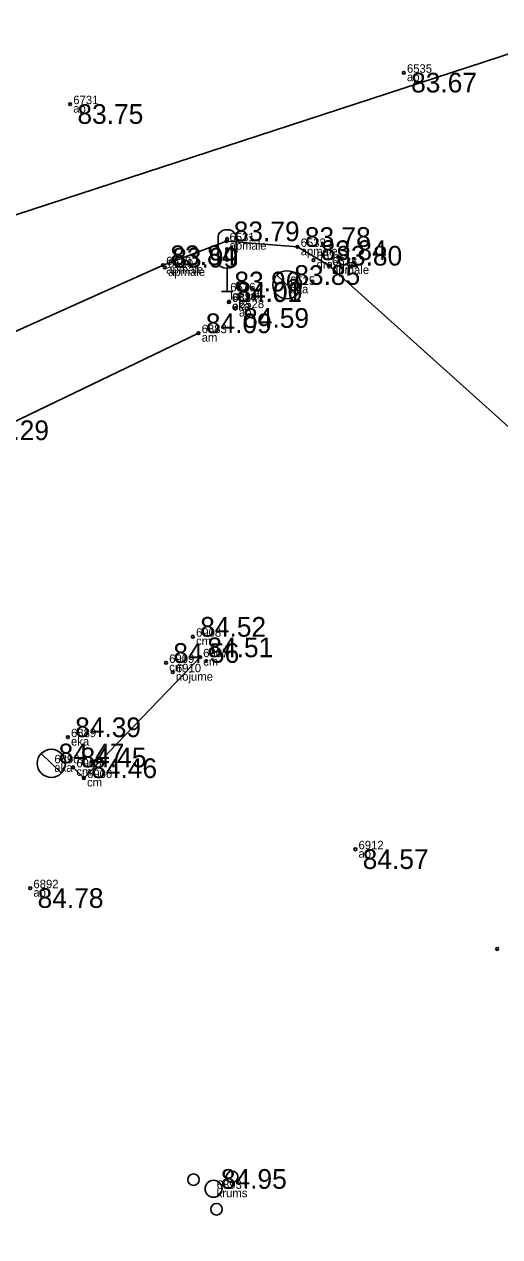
# Model space of a CAD drawing. Extents: x 614911 to 615803, y 262110 to 264311.
# Drawn here: x 615249.41 to 615266.31, y 262526.26 to 262569.35 of the extents above; entities that cross this region are included whole.
import ezdxf

# ---------------------------------------------------------------- set-up
doc = ezdxf.new("R2010")
doc.units = 0
for name, color, linetype in [('Level 1', 7, 'Continuous'), ('Level 12', 7, 'Continuous'), ('Level 16', 7, 'Continuous'), ('Level 37', 7, 'Continuous'), ('Level 53', 7, 'Continuous'), ('Level 54', 7, 'Continuous'), ('Level 57', 7, 'Continuous'), ('Level 58', 7, 'Continuous')]:
    doc.layers.add(name, color=color, linetype=linetype)

msp = doc.modelspace()

# ---------------------------------------------------------------- linework, layer by layer
at = {"layer": 'Level 1'}
for centre, radius in [((615256.802, 262528.386), 0.207), ((615255.427, 262528.285), 0.204), ((615256.141, 262527.961), 0.301), ((615256.244, 262527.233), 0.205)]:
    msp.add_circle(centre, radius, dxfattribs=at)
at = {"layer": 'Level 12'}
for p, q in [((615258.392, 262560.439), (615259.11, 262559.743)), ((615258.751, 262560.091), (615258.75, 262560.09)), ((615250.013, 262543.431), (615250.731, 262542.735)), ((615250.372, 262543.083), (615250.371, 262543.082))]:
    msp.add_line(p, q, dxfattribs=at)
for centre in [(615258.751, 262560.091), (615250.372, 262543.083)]:
    msp.add_circle(centre, 0.5, dxfattribs=at)
at = {"layer": 'Level 16'}
for p, q in [((615256.302, 262561.808), (615256.302, 262560.862)), ((615256.944, 262561.808), (615256.944, 262560.862)), ((615256.623, 262560.688), (615256.623, 262559.859)), ((615256.423, 262559.859), (615256.623, 262559.859)), ((615256.623, 262559.859), (615256.823, 262559.859))]:
    msp.add_line(p, q, dxfattribs=at)
for centre in [(615256.623, 262561.719), (615256.623, 262561.359), (615256.623, 262560.979)]:
    msp.add_circle(centre, 0.05, dxfattribs=at)
for centre, ratio, start_param, end_param in [((615256.623, 262561.808), 0.760342, 0, 3.141593), ((615256.623, 262560.862), 0.542056, 3.141593, 6.283185)]:
    msp.add_ellipse(centre, major_axis=(0.321, 0), ratio=ratio, start_param=start_param, end_param=end_param, dxfattribs=at)
at = {"layer": 'Level 37'}
for points in [[(615457.356, 262631.081), (615418.128, 262618.058), (615393.754, 262609.896), (615371.98, 262602.687), (615338.025, 262591.236), (615307.145, 262581.538), (615241.041, 262559.945), (615223.546, 262552.282)], [(615305.711, 262520.305), (615305.035, 262521.061), (615300.079, 262524.986), (615283.388, 262539.926), (615275.352, 262547.197), (615260.244, 262560.777), (615259.126, 262561.441), (615256.598, 262561.642), (615254.346, 262560.792)], [(615254.346, 262560.792), (615243.383, 262555.871), (615236.021, 262552.487), (615232.793, 262549.846), (615230.539, 262546.557), (615229.608, 262539.718), (615229.798, 262537.742), (615236, 262503.867)], [(615239.65, 262486.346), (615242.619, 262487.458), (615239.15, 262503.973), (615232.793, 262537.845), (615232.824, 262539.909), (615233.444, 262544.601), (615235.556, 262547.934), (615237.603, 262549.605), (615247.69, 262554.573), (615255.607, 262558.375)], [(615255.66, 262546.855), (615251.532, 262542.561), (615251.154, 262542.941)]]:
    msp.add_lwpolyline(points, dxfattribs=at)
at = {"layer": 'Level 57'}
for centre in [(615262.903, 262567.63), (615251.043, 262566.514), (615256.598, 262561.642), (615259.126, 262561.441), (615259.692, 262560.972), (615254.346, 262560.792), (615254.411, 262560.707), (615260.244, 262560.777), (615256.681, 262559.48), (615256.695, 262559.493), (615256.933, 262559.264), (615255.607, 262558.375), (615255.407, 262547.585), (615254.453, 262546.654), (615255.66, 262546.855), (615254.692, 262546.321), (615250.962, 262544.015), (615251.154, 262542.941), (615251.532, 262542.561), (615261.182, 262540.029), (615249.627, 262538.645), (615266.223, 262536.485)]:
    msp.add_circle(centre, 0.05, dxfattribs=at)
at = {"layer": 'Level 58'}
for centre in [(615262.903, 262567.63), (615251.043, 262566.514), (615256.598, 262561.642), (615259.126, 262561.441), (615259.692, 262560.972), (615254.346, 262560.792), (615254.411, 262560.707), (615260.244, 262560.777), (615256.681, 262559.48), (615256.695, 262559.493), (615256.933, 262559.264), (615255.607, 262558.375), (615255.407, 262547.585), (615254.453, 262546.654), (615255.66, 262546.855), (615254.692, 262546.321), (615250.962, 262544.015), (615251.154, 262542.941), (615251.532, 262542.561), (615261.182, 262540.029), (615249.627, 262538.645), (615266.223, 262536.485)]:
    msp.add_circle(centre, 0.05, dxfattribs=at)

# ---------------------------------------------------------------- texts
at = {"layer": 'Level 53'}
for s, p in [(' ap', (615262.903, 262567.33)), (' ap', (615251.043, 262566.214)), (' apmale', (615256.598, 262561.342)), (' apmale', (615259.126, 262561.141)), (' drasu.z', (615259.692, 262560.672)), (' apmale', (615254.346, 262560.492)), (' apmale', (615254.411, 262560.407)), (' apmale', (615260.244, 262560.477)), (' aka', (615258.751, 262559.791)), (' luksaf', (615256.623, 262559.559)), (' eka', (615256.681, 262559.18)), (' eka', (615256.695, 262559.193)), (' ap', (615256.933, 262558.964)), (' am', (615255.607, 262558.075)), (' cm', (615255.407, 262547.285)), (' cm', (615255.66, 262546.555)), (' cm', (615254.453, 262546.354)), (' nojume', (615254.692, 262546.021)), (' eka', (615250.962, 262543.715)), (' aka', (615250.372, 262542.783)), (' cm', (615251.154, 262542.641)), (' cm', (615251.532, 262542.261)), (' ap', (615261.182, 262539.729)), (' ap', (615249.627, 262538.345)), (' krums', (615256.141, 262527.661))]:
    msp.add_text(s, height=0.3, dxfattribs=at).set_placement(p)
at = {"layer": 'Level 54'}
for s, p in [(' 6535', (615262.903, 262567.63)), (' 6731', (615251.043, 262566.514)), (' 6531', (615256.598, 262561.642)), (' 6532', (615259.126, 262561.441)), (' 6529', (615254.346, 262560.792)), (' 6530', (615254.411, 262560.707)), (' 6534', (615259.692, 262560.972)), (' 6533', (615260.244, 262560.777)), (' 6526', (615256.623, 262559.859)), (' 6525', (615258.751, 262560.091)), (' 6527', (615256.681, 262559.48)), (' 6884', (615256.695, 262559.493)), (' 6528', (615256.933, 262559.264)), (' 6883', (615255.607, 262558.375)), (' 6908', (615255.407, 262547.585)), (' 6907', (615255.66, 262546.855)), (' 6909', (615254.453, 262546.654)), (' 6910', (615254.692, 262546.321)), (' 6889', (615250.962, 262544.015)), (' 6890', (615250.372, 262543.083)), (' 6905', (615251.154, 262542.941)), (' 6906', (615251.532, 262542.561)), (' 6912', (615261.182, 262540.029)), (' 6892', (615249.627, 262538.645)), (' 6893', (615256.141, 262527.961))]:
    msp.add_text(s, height=0.3, dxfattribs=at).set_placement(p)
at = {"layer": 'Level 58'}
for s, p in [(' 83.67', (615262.903, 262566.93)), (' 83.75', (615251.043, 262565.814)), (' 83.79', (615256.598, 262561.642)), (' 83.78', (615259.126, 262561.441)), (' 83.84', (615254.346, 262560.792)), (' 83.99', (615254.411, 262560.707)), (' 83.84', (615259.692, 262560.972)), (' 83.80', (615260.244, 262560.777)), (' 83.96', (615256.623, 262559.859)), (' 83.85', (615258.751, 262560.091)), (' 84.01', (615256.681, 262559.48)), (' 84.00', (615256.695, 262559.493)), (' 84.59', (615256.933, 262558.564)), (' 84.09', (615255.607, 262558.375)), (' 84.29', (615247.69, 262554.573)), (' 84.52', (615255.407, 262547.585)), (' 84.51', (615255.66, 262546.855)), (' 84.56', (615254.453, 262546.654)), (' 84.39', (615250.962, 262544.015)), (' 84.47', (615250.372, 262543.083)), (' 84.45', (615251.154, 262542.941)), (' 84.46', (615251.532, 262542.561)), (' 84.57', (615261.182, 262539.329)), (' 84.78', (615249.627, 262537.945)), (' 84.95', (615256.141, 262527.961))]:
    msp.add_text(s, height=0.7, dxfattribs=at).set_placement(p)

doc.saveas('drawing.dxf')
